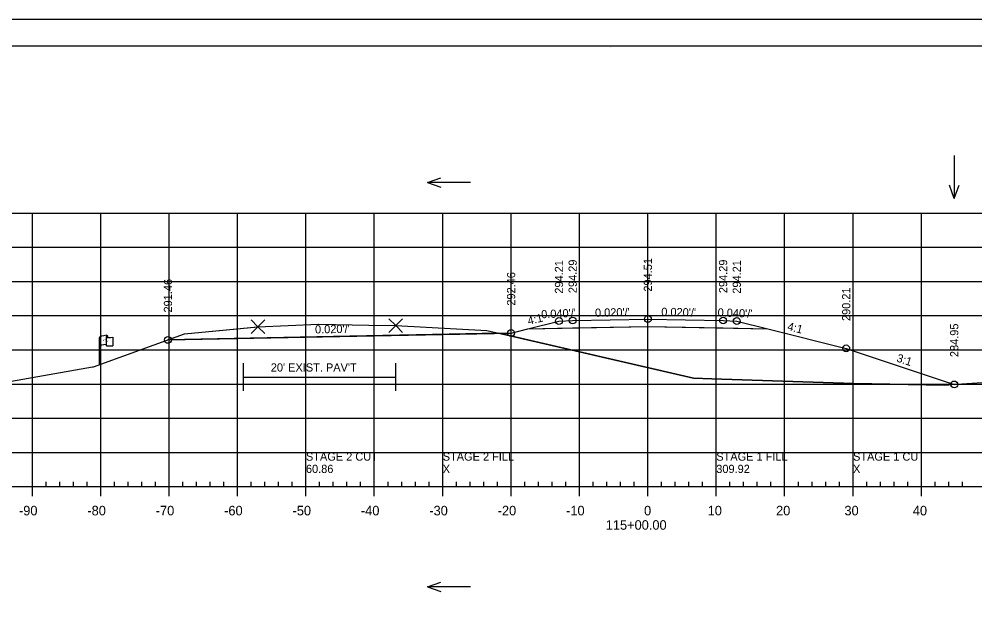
# Model space of a CAD drawing. Extents: x 1370843 to 1371177, y 380307 to 382654.
# Drawn here: x 1370921.8 to 1371061.5, y 381501.3 to 381587.5 of the extents above; entities that cross this region are included whole.
import ezdxf

# ---------------------------------------------------------------- set-up
doc = ezdxf.new("R2010")
doc.units = 0
for name, color, linetype in [('R_Alt Surface', 7, 'Continuous'), ('R_Axis', 7, 'Continuous'), ('R_Axis Annot', 7, 'Continuous'), ('R_Border', 7, 'Continuous'), ('R_Exist Surface', 7, 'Continuous'), ('R_Exist Surface Annot', 7, 'Continuous'), ('R_Fin Surface', 7, 'Continuous'), ('R_Fin Surface Annot', 7, 'Continuous'), ('R_Grid', 7, 'Continuous'), ('R_No Plot', 7, 'Continuous'), ('R_ROW', 7, 'Continuous'), ('R_Water Annot', 7, 'Continuous')]:
    doc.layers.add(name, color=color, linetype=linetype)

msp = doc.modelspace()

# ---------------------------------------------------------------- linework, layer by layer
at = {"layer": 'R_Alt Surface'}
msp.add_lwpolyline([(1370996.17, 381542.22), (1371002.71, 381542.35), (1371013.71, 381542.57), (1371024.71, 381542.35), (1371031.25, 381542.22)], dxfattribs=at)
at = {"layer": 'R_Axis'}
for p, q in [((1370868.71, 381519.14), (1371158.71, 381519.14)), ((1370923.71, 381517.74), (1370923.71, 381519.14)), ((1370925.71, 381519.14), (1370925.71, 381519.84)), ((1370927.71, 381519.14), (1370927.71, 381519.84)), ((1370929.71, 381519.14), (1370929.71, 381519.84)), ((1370931.71, 381519.14), (1370931.71, 381519.84)), ((1370933.71, 381517.74), (1370933.71, 381519.14)), ((1370935.71, 381519.14), (1370935.71, 381519.84)), ((1370937.71, 381519.14), (1370937.71, 381519.84)), ((1370939.71, 381519.14), (1370939.71, 381519.84)), ((1370941.71, 381519.14), (1370941.71, 381519.84)), ((1370943.71, 381517.74), (1370943.71, 381519.14)), ((1370945.71, 381519.14), (1370945.71, 381519.84)), ((1370947.71, 381519.14), (1370947.71, 381519.84)), ((1370949.71, 381519.14), (1370949.71, 381519.84)), ((1370951.71, 381519.14), (1370951.71, 381519.84)), ((1370953.71, 381517.74), (1370953.71, 381519.14)), ((1370955.71, 381519.14), (1370955.71, 381519.84)), ((1370957.71, 381519.14), (1370957.71, 381519.84)), ((1370959.71, 381519.14), (1370959.71, 381519.84)), ((1370961.71, 381519.14), (1370961.71, 381519.84)), ((1370963.71, 381517.74), (1370963.71, 381519.14)), ((1370965.71, 381519.14), (1370965.71, 381519.84)), ((1370967.71, 381519.14), (1370967.71, 381519.84)), ((1370969.71, 381519.14), (1370969.71, 381519.84)), ((1370971.71, 381519.14), (1370971.71, 381519.84)), ((1370973.71, 381517.74), (1370973.71, 381519.14)), ((1370975.71, 381519.14), (1370975.71, 381519.84)), ((1370977.71, 381519.14), (1370977.71, 381519.84)), ((1370979.71, 381519.14), (1370979.71, 381519.84)), ((1370981.71, 381519.14), (1370981.71, 381519.84)), ((1370983.71, 381517.74), (1370983.71, 381519.14)), ((1370985.71, 381519.14), (1370985.71, 381519.84)), ((1370987.71, 381519.14), (1370987.71, 381519.84)), ((1370989.71, 381519.14), (1370989.71, 381519.84)), ((1370991.71, 381519.14), (1370991.71, 381519.84)), ((1370993.71, 381517.74), (1370993.71, 381519.14)), ((1370995.71, 381519.14), (1370995.71, 381519.84)), ((1370997.71, 381519.14), (1370997.71, 381519.84)), ((1370999.71, 381519.14), (1370999.71, 381519.84)), ((1371001.71, 381519.14), (1371001.71, 381519.84)), ((1371003.71, 381517.74), (1371003.71, 381519.14)), ((1371005.71, 381519.14), (1371005.71, 381519.84)), ((1371007.71, 381519.14), (1371007.71, 381519.84)), ((1371009.71, 381519.14), (1371009.71, 381519.84)), ((1371011.71, 381519.14), (1371011.71, 381519.84)), ((1371013.71, 381517.74), (1371013.71, 381519.14)), ((1371015.71, 381519.14), (1371015.71, 381519.84)), ((1371017.71, 381519.14), (1371017.71, 381519.84)), ((1371019.71, 381519.14), (1371019.71, 381519.84)), ((1371021.71, 381519.14), (1371021.71, 381519.84)), ((1371023.71, 381517.74), (1371023.71, 381519.14)), ((1371025.71, 381519.14), (1371025.71, 381519.84)), ((1371027.71, 381519.14), (1371027.71, 381519.84)), ((1371029.71, 381519.14), (1371029.71, 381519.84)), ((1371031.71, 381519.14), (1371031.71, 381519.84)), ((1371033.71, 381517.74), (1371033.71, 381519.14)), ((1371035.71, 381519.14), (1371035.71, 381519.84)), ((1371037.71, 381519.14), (1371037.71, 381519.84)), ((1371039.71, 381519.14), (1371039.71, 381519.84)), ((1371041.71, 381519.14), (1371041.71, 381519.84)), ((1371043.71, 381517.74), (1371043.71, 381519.14)), ((1371045.71, 381519.14), (1371045.71, 381519.84)), ((1371047.71, 381519.14), (1371047.71, 381519.84)), ((1371049.71, 381519.14), (1371049.71, 381519.84)), ((1371051.71, 381519.14), (1371051.71, 381519.84)), ((1371053.71, 381517.74), (1371053.71, 381519.14)), ((1371055.71, 381519.14), (1371055.71, 381519.84)), ((1371057.71, 381519.14), (1371057.71, 381519.84)), ((1371059.71, 381519.14), (1371059.71, 381519.84))]:
    msp.add_line(p, q, dxfattribs=at)
at = {"layer": 'R_Border'}
for p, q in [((1370855.71, 381583.6), (1371171.89, 381583.6)), ((1371008.23, 381583.34), (1371008.23, 381583.34)), ((1371008.23, 381583.34), (1371008.23, 381583.34))]:
    msp.add_line(p, q, dxfattribs=at)
at = {"layer": 'R_Exist Surface'}
msp.add_lwpolyline([(1370920.65, 381534.56), (1370932.5, 381536.64), (1370932.61, 381536.65), (1370932.63, 381536.66), (1370945.94, 381541.47), (1370956.62, 381542.51), (1370956.68, 381542.51), (1370965.56, 381542.88), (1370965.6, 381542.88), (1370972.9, 381542.75), (1370976.82, 381542.68), (1370976.85, 381542.68), (1370990.14, 381541.95), (1370990.34, 381541.94), (1370991.04, 381541.77), (1371020.4, 381535.02), (1371023.08, 381534.92), (1371043.8, 381534.22), (1371057.08, 381533.99), (1371057.51, 381534.01), (1371057.7, 381534.03), (1371058.16, 381534.06), (1371078.06, 381535.41)], dxfattribs=at)
at = {"layer": 'R_Exist Surface Annot'}
for p, q in [((1370954.56, 381533.17), (1370954.56, 381537.17)), ((1370976.85, 381533.17), (1370976.85, 381537.17)), ((1370954.56, 381535.17), (1370976.85, 381535.17))]:
    msp.add_line(p, q, dxfattribs=at)
at = {"layer": 'R_Fin Surface'}
msp.add_lwpolyline([(1370943.53, 381540.6), (1370983.71, 381541.4), (1370993.71, 381541.6), (1370996.17, 381542.22), (1371000.71, 381543.35), (1371002.71, 381543.43), (1371013.71, 381543.65), (1371024.71, 381543.43), (1371026.71, 381543.35), (1371031.25, 381542.22), (1371042.71, 381539.35), (1371058.51, 381534.08)], dxfattribs=at)
at = {"layer": 'R_Grid'}
for p, q in [((1370868.71, 381559.14), (1371158.71, 381559.14)), ((1370923.71, 381519.14), (1370923.71, 381559.14)), ((1370933.71, 381519.14), (1370933.71, 381559.14)), ((1370943.71, 381519.14), (1370943.71, 381559.14)), ((1370953.71, 381519.14), (1370953.71, 381559.14)), ((1370963.71, 381519.14), (1370963.71, 381559.14)), ((1370973.71, 381519.14), (1370973.71, 381559.14)), ((1370983.71, 381519.14), (1370983.71, 381559.14)), ((1370993.71, 381519.14), (1370993.71, 381559.14)), ((1371003.71, 381519.14), (1371003.71, 381559.14)), ((1371013.71, 381519.14), (1371013.71, 381559.14)), ((1371023.71, 381519.14), (1371023.71, 381559.14)), ((1371033.71, 381519.14), (1371033.71, 381559.14)), ((1371043.71, 381519.14), (1371043.71, 381559.14)), ((1371053.71, 381519.14), (1371053.71, 381559.14)), ((1370868.71, 381554.14), (1371158.71, 381554.14)), ((1370868.71, 381549.14), (1371158.71, 381549.14)), ((1370868.71, 381544.14), (1371158.71, 381544.14)), ((1370868.71, 381539.14), (1371158.71, 381539.14)), ((1370868.71, 381534.14), (1371158.71, 381534.14)), ((1370868.71, 381529.14), (1371158.71, 381529.14)), ((1370868.71, 381524.14), (1371158.71, 381524.14)), ((1370868.71, 381519.14), (1371158.71, 381519.14))]:
    msp.add_line(p, q, dxfattribs=at)
at = {"layer": 'R_No Plot'}
msp.add_line((1370843.31, 381587.49), (1371176.64, 381587.49), dxfattribs=at)
for points in [[(1370843.3, 381587.49), (1371176.64, 381587.49), (1371176.64, 381374.16), (1370843.3, 381374.16)], [(1371089.63, 381583.6), (1371089.63, 381573.72), (1371125.36, 381573.72), (1371125.36, 381570.8), (1371148.56, 381570.8), (1371148.56, 381546.47), (1371171.89, 381546.47), (1371171.89, 381378.14), (1370855.71, 381378.14), (1370855.71, 381583.6)], [(1370943.53, 381540.6), (1370945.94, 381541.47), (1370956.68, 381542.51), (1370965.56, 381542.88), (1370972.9, 381542.75), (1370976.82, 381542.68), (1370976.85, 381542.68), (1370990.14, 381541.95), (1370990.34, 381541.94), (1370991.04, 381541.77), (1370991.94, 381541.57)], [(1370991.94, 381541.57), (1370993.71, 381541.6), (1370996.17, 381542.22), (1371013.71, 381542.57), (1371031.25, 381542.22), (1371042.71, 381539.35), (1371058.51, 381534.08), (1371057.7, 381534.03), (1371057.51, 381534.01), (1371057.08, 381533.99), (1371043.8, 381534.22), (1371023.08, 381534.92), (1371020.4, 381535.02)]]:
    msp.add_lwpolyline(points, close=True, dxfattribs=at)
for points in [[(1370956.68, 381542.51), (1370955.68, 381543.51), (1370956.68, 381542.51), (1370955.68, 381541.51), (1370956.68, 381542.51), (1370957.68, 381541.51), (1370956.68, 381542.51), (1370957.68, 381543.51)], [(1370976.85, 381542.68), (1370975.85, 381543.68), (1370976.85, 381542.68), (1370975.85, 381541.68), (1370976.85, 381542.68), (1370977.85, 381541.68), (1370976.85, 381542.68), (1370977.85, 381543.68)]]:
    msp.add_lwpolyline(points, dxfattribs=at)
for centre in [(1371013.71, 381543.65), (1371000.71, 381543.35), (1371002.71, 381543.43), (1371024.71, 381543.43), (1371026.71, 381543.35), (1370993.71, 381541.6), (1370943.53, 381540.6), (1371042.71, 381539.35), (1371058.51, 381534.08)]:
    msp.add_circle(centre, 0.5, dxfattribs=at)
at = {"layer": 'R_ROW'}
for p, q in [((1370933.52, 381536.98), (1370933.52, 381540.94)), ((1370934.51, 381541.03), (1370934.51, 381541.02)), ((1370934.51, 381541.02), (1370934.51, 381539.79)), ((1370934.68, 381541.19), (1370934.68, 381540.95)), ((1370935.45, 381540.99), (1370935.45, 381539.75))]:
    msp.add_line(p, q, dxfattribs=at)
for centre, radius, start, end in [((1370934.6, 381541.19), 0.0783, 263.0712, 93.9564), ((1370934.59, 381541.03), 0.078, 88.6458, 274.2828), ((1370934.59, 381539.79), 0.0783, 180, 273.9564)]:
    msp.add_arc(centre, radius, start, end, dxfattribs=at)
for centre, major_axis, ratio, start_param, end_param in [((1370935.1, 381540.98), (-1.58, -0.04), 0.19887, 5.030368, 6.283185), ((1370935.1, 381539.66), (-1.58, -0.04), 0.19887, 5.083035, 6.194897), ((1370935.81, 381541.09), (-1.23, -0.13), 0.052933, 0.159456, 1.268315), ((1370935.81, 381539.85), (-1.23, -0.13), 0.052933, 0.159456, 1.268315)]:
    msp.add_ellipse(centre, major_axis=major_axis, ratio=ratio, start_param=start_param, end_param=end_param, dxfattribs=at)
at = {"layer": 'R_Water Annot'}
for p, q in [((1371058.51, 381567.56), (1371058.51, 381561.27)), ((1370981.5, 381563.61), (1370983.42, 381564.31)), ((1370987.78, 381563.61), (1370981.5, 381563.61)), ((1370981.5, 381563.61), (1370983.42, 381562.91)), ((1371058.51, 381561.27), (1371057.81, 381563.2)), ((1371058.51, 381561.27), (1371059.21, 381563.2)), ((1370981.5, 381504.5), (1370983.42, 381505.2)), ((1370987.78, 381504.5), (1370981.5, 381504.5)), ((1370981.5, 381504.5), (1370983.42, 381503.8))]:
    msp.add_line(p, q, dxfattribs=at)

# ---------------------------------------------------------------- texts
at = {"layer": 'R_Axis Annot'}
for s, p in [('-90', (1370921.75, 381514.94)), ('-80', (1370931.75, 381514.94)), ('-70', (1370941.75, 381514.94)), ('-60', (1370951.75, 381514.94)), ('-50', (1370961.75, 381514.94)), ('-40', (1370971.75, 381514.94)), ('-30', (1370981.75, 381514.94)), ('-20', (1370991.75, 381514.94)), ('-10', (1371001.75, 381514.94)), ('0', (1371013.15, 381514.94)), ('10', (1371022.45, 381514.94)), ('20', (1371032.45, 381514.94)), ('30', (1371042.45, 381514.94)), ('40', (1371052.45, 381514.94)), ('115+00.00', (1371007.55, 381512.84))]:
    msp.add_text(s, height=1.4, dxfattribs=at).set_placement(p)
at = {"layer": 'R_Exist Surface Annot'}
msp.add_text("20' EXIST. PAV'T", height=1.2, dxfattribs=at).set_placement((1370958.57, 381535.97))
at = {"layer": 'R_Fin Surface Annot'}
for s, rotation, p in [('294.51', 90, (1371014.31, 381547.65)), ('294.21', 90, (1371001.31, 381547.35)), ('294.29', 90, (1371003.31, 381547.43)), ('294.29', 90, (1371025.31, 381547.43)), ('294.21', 90, (1371027.31, 381547.35)), ('292.46', 90, (1370994.31, 381545.6)), ('291.46', 90, (1370944.13, 381544.6)), ('290.21', 90, (1371043.31, 381543.35)), ('4:1', 14.0362, (1370996.28, 381542.76)), ("0.040'/'", 2.2906, (1370998.13, 381543.75)), ("0.020'/'", 1.1458, (1371005.99, 381543.97)), ("0.020'/'", 358.8542, (1371015.66, 381544.11)), ("0.040'/'", 357.7094, (1371023.89, 381544.03)), ("0.020'/'", 1.1458, (1370965.05, 381541.53)), ('4:1', 345.9638, (1371034.02, 381542.04)), ('284.95', 90, (1371059.11, 381538.08)), ('3:1', 341.5651, (1371049.98, 381537.46))]:
    msp.add_text(s, height=1.2, rotation=rotation, dxfattribs=at).set_placement(p)
at = {"layer": 'R_No Plot'}
for s, p in [('STAGE 2 CUT', (1370963.71, 381522.94)), ('STAGE 2 FILL', (1370983.71, 381522.94)), ('STAGE 1 FILL', (1371023.71, 381522.94)), ('STAGE 1 CUT', (1371043.71, 381522.94)), ('60.86', (1370963.71, 381521.14)), ('X', (1370983.71, 381521.14)), ('309.92', (1371023.71, 381521.14)), ('X', (1371043.71, 381521.14))]:
    msp.add_text(s, height=1.2, dxfattribs=at).set_placement(p)
at = {"layer": 'R_ROW'}
for s, height, rotation, p in [('R ', 0.2, 9.9884, (1370934.04, 381540.44)), (' O', 0.2, 9.9884, (1370934.18, 381540.48)), ('W', 0.2, 351.1788, (1370934.51, 381540.31)), ('DWB 11-9-07', 0.001, 90, (1370934.68, 381540.95)), ('DWB 11-9-07', 0.001, 5.0717, (1370935.44, 381539.75)), ('DWB 11-9-07', 0.001, 90, (1370933.52, 381536.98))]:
    msp.add_text(s, height=height, rotation=rotation, dxfattribs=at).set_placement(p)

doc.saveas('drawing.dxf')
